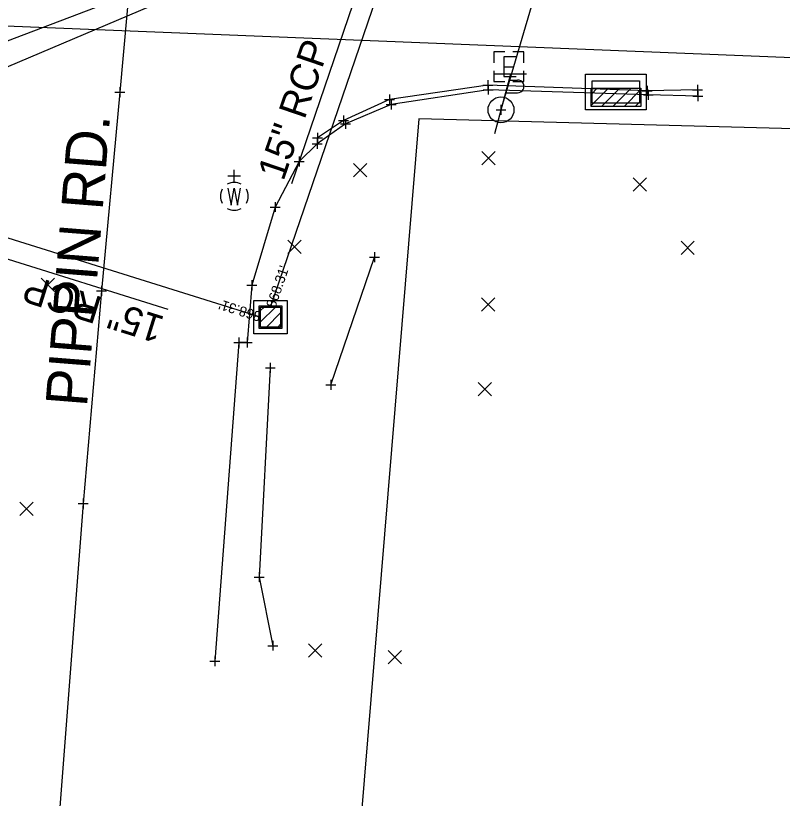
# Model space of a CAD drawing. Extents: x 1380550 to 1381945, y 468927 to 470496.
# Drawn here: x 1381608.3 to 1381685.3, y 470149.2 to 470227.8 of the extents above; entities that cross this region are included whole.
import ezdxf

# ---------------------------------------------------------------- set-up
doc = ezdxf.new("R2010")
doc.units = 0
for name, color, linetype in [('DR_X_Cells', 7, 'Continuous'), ('DR_X_Ditch', 7, 'Continuous'), ('DR_X_Storm_Sewer', 7, 'Continuous'), ('DR_X_Text', 7, 'Continuous'), ('GK_Drainage_Nodes', 7, 'Continuous'), ('PV_X_COP', 7, 'Continuous'), ('PV_X_Curb', 7, 'Continuous'), ('PV_X_EOP', 7, 'Continuous'), ('RD_X_Text', 7, 'Continuous'), ('RW_X_Esmt_General', 7, 'Continuous'), ('SC_Scratch1', 7, 'Continuous'), ('SV_X_Random_Point', 7, 'Continuous'), ('SV_X_Shot_Marker', 7, 'Continuous'), ('SV_X_Top_of_Bank', 7, 'Continuous'), ('UT_X_Electric', 7, 'Continuous'), ('UT_X_Electric_Cells', 7, 'Continuous'), ('UT_X_Misc_Cells', 7, 'Continuous'), ('UT_X_Telecom', 7, 'Continuous'), ('UT_X_Water_Cells', 7, 'Continuous')]:
    doc.layers.add(name, color=color, linetype=linetype)

msp = doc.modelspace()

# ---------------------------------------------------------------- linework, layer by layer
at = {"layer": 'DR_X_Cells'}
for p, q in [((1381666.074, 470218.798), (1381667.828, 470220.557)), ((1381666.074, 470219.931), (1381666.698, 470220.557)), ((1381667.13, 470218.724), (1381668.958, 470220.557)), ((1381668.259, 470218.724), (1381670.088, 470220.557)), ((1381669.389, 470218.724), (1381671.074, 470220.413)), ((1381670.519, 470218.724), (1381671.074, 470219.28)), ((1381632.757, 470196.945), (1381634.516, 470198.703)), ((1381632.757, 470198.076), (1381633.385, 470198.703)), ((1381633.356, 470196.412), (1381635.049, 470198.105)), ((1381634.487, 470196.412), (1381635.049, 470196.973))]:
    msp.add_line(p, q, dxfattribs=at)
for points in [[(1381665.532, 470221.974), (1381671.616, 470221.974), (1381671.616, 470218.39), (1381665.532, 470218.39)], [(1381666.199, 470221.307), (1381670.949, 470221.307), (1381670.949, 470219.057), (1381666.199, 470219.057)], [(1381666.074, 470220.557), (1381671.074, 470220.557), (1381671.074, 470218.724), (1381666.074, 470218.724)], [(1381632.236, 470199.224), (1381635.57, 470199.224), (1381635.57, 470195.891), (1381632.236, 470195.891)], [(1381632.757, 470198.703), (1381635.049, 470198.703), (1381635.049, 470196.412), (1381632.757, 470196.412)], [(1381632.903, 470198.558), (1381634.903, 470198.558), (1381634.903, 470196.558), (1381632.903, 470196.558)]]:
    msp.add_lwpolyline(points, close=True, dxfattribs=at)
at = {"layer": 'DR_X_Ditch'}
msp.add_lwpolyline([(1381633.879, 470192.462), (1381632.757, 470171.449), (1381634.143, 470164.552)], dxfattribs=at)
at = {"layer": 'DR_X_Storm_Sewer'}
for p, q in [((1381633.903, 470198.558), (1381646.794, 470236.273)), ((1381906.161, 470214.727), (1381603.055, 470226.96)), ((1381632.903, 470197.558), (1381601.076, 470207.52))]:
    msp.add_line(p, q, dxfattribs=at)
at = {"layer": 'DR_X_Text'}
for p, q in [((1381642.166, 470228.993), (1381635.993, 470210.933)), ((1381605.369, 470204.055), (1381623.583, 470198.353))]:
    msp.add_line(p, q, dxfattribs=at)
at = {"layer": 'GK_Drainage_Nodes'}
for p, q in [((1381668.574, 470221.974), (1381668.574, 470221.974)), ((1381668.574, 470221.307), (1381668.574, 470221.307)), ((1381666.199, 470220.182), (1381666.199, 470220.182)), ((1381668.574, 470220.557), (1381668.574, 470220.557)), ((1381668.574, 470220.557), (1381668.574, 470220.557)), ((1381668.574, 470220.182), (1381668.574, 470220.182)), ((1381670.949, 470220.182), (1381670.949, 470220.182)), ((1381668.574, 470219.057), (1381668.574, 470219.057)), ((1381668.574, 470218.39), (1381668.574, 470218.39)), ((1381633.903, 470199.224), (1381633.903, 470199.224)), ((1381633.903, 470198.558), (1381633.903, 470198.558)), ((1381632.903, 470197.558), (1381632.903, 470197.558)), ((1381633.903, 470197.558), (1381633.903, 470197.558)), ((1381633.903, 470197.558), (1381633.903, 470197.558)), ((1381633.903, 470197.558), (1381633.903, 470197.558)), ((1381634.903, 470197.558), (1381634.903, 470197.558)), ((1381633.903, 470196.558), (1381633.903, 470196.558)), ((1381633.903, 470195.891), (1381633.903, 470195.891))]:
    msp.add_line(p, q, dxfattribs=at)
at = {"layer": 'PV_X_COP'}
msp.add_lwpolyline([(1381627.408, 470324.235), (1381625.025, 470294.425), (1381622.344, 470259.947), (1381618.765, 470220.138), (1381616.919, 470200.188), (1381615.103, 470178.831), (1381610.946, 470124.776), (1381606.492, 470071.232), (1381602.26, 470019.361), (1381598.177, 469969.796), (1381595.011, 469928.064), (1381590.91, 469878.811), (1381589.36, 469859.114), (1381585.986, 469815.579), (1381581.288, 469760.779)], dxfattribs=at)
at = {"layer": 'PV_X_Curb'}
msp.add_lwpolyline([(1381676.791, 470219.75), (1381671.827, 470219.886), (1381655.739, 470220.402), (1381646.018, 470218.916), (1381641.43, 470216.955), (1381638.594, 470214.962)], dxfattribs=at)
at = {"layer": 'PV_X_EOP'}
msp.add_lwpolyline([(1381676.765, 470220.385), (1381671.708, 470220.296), (1381655.718, 470220.85), (1381645.835, 470219.405), (1381641.211, 470217.307), (1381638.618, 470215.563), (1381638.594, 470214.962), (1381636.765, 470213.193), (1381634.363, 470208.616), (1381632.01, 470200.77), (1381631.562, 470195.02), (1381630.708, 470194.999), (1381628.299, 470162.981)], dxfattribs=at)
at = {"layer": 'RW_X_Esmt_General'}
msp.add_lwpolyline([(1381783.194, 470213.888), (1381648.776, 470217.487), (1381563.79, 469189.032)], dxfattribs=at)
at = {"layer": 'SV_X_Random_Point'}
for p, q in [((1381655.103, 470212.868), (1381656.437, 470214.204)), ((1381655.103, 470214.204), (1381656.437, 470212.868)), ((1381642.237, 470211.656), (1381643.571, 470212.991)), ((1381642.237, 470212.991), (1381643.571, 470211.656)), ((1381670.301, 470210.201), (1381671.635, 470211.536)), ((1381670.301, 470211.536), (1381671.635, 470210.201)), ((1381635.644, 470203.939), (1381636.978, 470205.274)), ((1381635.644, 470205.274), (1381636.978, 470203.939)), ((1381675.11, 470203.861), (1381676.444, 470205.196)), ((1381675.11, 470205.196), (1381676.444, 470203.861)), ((1381610.886, 470200.127), (1381612.22, 470201.462)), ((1381610.886, 470201.462), (1381612.22, 470200.127)), ((1381655.079, 470198.144), (1381656.413, 470199.479)), ((1381655.079, 470199.479), (1381656.413, 470198.144)), ((1381654.744, 470189.642), (1381656.078, 470190.977)), ((1381654.744, 470190.977), (1381656.078, 470189.642)), ((1381608.724, 470177.633), (1381610.058, 470178.968)), ((1381608.724, 470178.968), (1381610.058, 470177.633)), ((1381637.706, 470163.411), (1381639.04, 470164.746)), ((1381637.706, 470164.746), (1381639.04, 470163.411)), ((1381645.711, 470162.721), (1381647.045, 470164.056)), ((1381645.711, 470164.056), (1381647.045, 470162.721))]:
    msp.add_line(p, q, dxfattribs=at)
at = {"layer": 'SV_X_Shot_Marker'}
for p, q in [((1381618.765, 470220.638), (1381618.765, 470219.638)), ((1381655.218, 470220.85), (1381656.218, 470220.85)), ((1381655.218, 470220.85), (1381656.218, 470220.85)), ((1381655.718, 470221.35), (1381655.718, 470220.35)), ((1381655.718, 470221.35), (1381655.718, 470220.35)), ((1381655.718, 470220.85), (1381655.718, 470220.85)), ((1381655.718, 470220.85), (1381655.718, 470220.85)), ((1381655.739, 470220.902), (1381655.739, 470219.902)), ((1381655.739, 470220.902), (1381655.739, 470219.902)), ((1381671.708, 470220.796), (1381671.708, 470219.796)), ((1381676.765, 470220.885), (1381676.765, 470219.885)), ((1381618.265, 470220.138), (1381619.265, 470220.138)), ((1381618.765, 470220.138), (1381618.765, 470220.138)), ((1381645.835, 470219.905), (1381645.835, 470218.905)), ((1381655.239, 470220.402), (1381656.239, 470220.402)), ((1381655.239, 470220.402), (1381656.239, 470220.402)), ((1381655.739, 470220.402), (1381655.739, 470220.402)), ((1381655.739, 470220.402), (1381655.739, 470220.402)), ((1381671.208, 470220.296), (1381672.208, 470220.296)), ((1381671.327, 470219.886), (1381672.327, 470219.886)), ((1381671.708, 470220.296), (1381671.708, 470220.296)), ((1381671.827, 470220.386), (1381671.827, 470219.386)), ((1381671.827, 470219.886), (1381671.827, 470219.886)), ((1381676.265, 470220.385), (1381677.265, 470220.385)), ((1381676.765, 470220.385), (1381676.765, 470220.385)), ((1381676.791, 470220.25), (1381676.791, 470219.25)), ((1381645.335, 470219.405), (1381646.335, 470219.405)), ((1381645.835, 470219.405), (1381645.835, 470219.405)), ((1381646.018, 470219.416), (1381646.018, 470218.416)), ((1381676.291, 470219.75), (1381677.291, 470219.75)), ((1381676.791, 470219.75), (1381676.791, 470219.75)), ((1381645.518, 470218.916), (1381646.518, 470218.916)), ((1381646.018, 470218.916), (1381646.018, 470218.916)), ((1381656.535, 470218.369), (1381657.535, 470218.369)), ((1381656.535, 470218.369), (1381657.535, 470218.369)), ((1381657.035, 470218.869), (1381657.035, 470217.869)), ((1381657.035, 470218.869), (1381657.035, 470217.869)), ((1381657.035, 470218.369), (1381657.035, 470218.369)), ((1381657.035, 470218.369), (1381657.035, 470218.369)), ((1381641.211, 470217.807), (1381641.211, 470216.807)), ((1381641.211, 470217.807), (1381641.211, 470216.807)), ((1381641.43, 470217.455), (1381641.43, 470216.455)), ((1381641.43, 470217.455), (1381641.43, 470216.455)), ((1381640.711, 470217.307), (1381641.711, 470217.307)), ((1381640.711, 470217.307), (1381641.711, 470217.307)), ((1381640.93, 470216.955), (1381641.93, 470216.955)), ((1381640.93, 470216.955), (1381641.93, 470216.955)), ((1381641.211, 470217.307), (1381641.211, 470217.307)), ((1381641.211, 470217.307), (1381641.211, 470217.307)), ((1381641.43, 470216.955), (1381641.43, 470216.955)), ((1381641.43, 470216.955), (1381641.43, 470216.955)), ((1381638.618, 470216.063), (1381638.618, 470215.063)), ((1381638.118, 470215.563), (1381639.118, 470215.563)), ((1381638.594, 470215.462), (1381638.594, 470214.462)), ((1381638.594, 470215.462), (1381638.594, 470214.462)), ((1381638.618, 470215.563), (1381638.618, 470215.563)), ((1381638.094, 470214.962), (1381639.094, 470214.962)), ((1381638.094, 470214.962), (1381639.094, 470214.962)), ((1381638.594, 470214.962), (1381638.594, 470214.962)), ((1381638.594, 470214.962), (1381638.594, 470214.962)), ((1381636.765, 470213.693), (1381636.765, 470212.693)), ((1381636.765, 470213.693), (1381636.765, 470212.693)), ((1381636.265, 470213.193), (1381637.265, 470213.193)), ((1381636.265, 470213.193), (1381637.265, 470213.193)), ((1381636.765, 470213.193), (1381636.765, 470213.193)), ((1381636.765, 470213.193), (1381636.765, 470213.193)), ((1381634.363, 470209.116), (1381634.363, 470208.116)), ((1381633.863, 470208.616), (1381634.863, 470208.616)), ((1381634.363, 470208.616), (1381634.363, 470208.616)), ((1381644.334, 470204.069), (1381644.334, 470203.069)), ((1381643.834, 470203.569), (1381644.834, 470203.569)), ((1381644.334, 470203.569), (1381644.334, 470203.569)), ((1381632.01, 470201.27), (1381632.01, 470200.27)), ((1381632.01, 470201.27), (1381632.01, 470200.27)), ((1381616.419, 470200.188), (1381617.419, 470200.188)), ((1381616.919, 470200.688), (1381616.919, 470199.688)), ((1381616.919, 470200.188), (1381616.919, 470200.188)), ((1381631.51, 470200.77), (1381632.51, 470200.77)), ((1381631.51, 470200.77), (1381632.51, 470200.77)), ((1381632.01, 470200.77), (1381632.01, 470200.77)), ((1381632.01, 470200.77), (1381632.01, 470200.77)), ((1381630.708, 470195.499), (1381630.708, 470194.499)), ((1381631.562, 470195.52), (1381631.562, 470194.52)), ((1381630.208, 470194.999), (1381631.208, 470194.999)), ((1381630.708, 470194.999), (1381630.708, 470194.999)), ((1381631.062, 470195.02), (1381632.062, 470195.02)), ((1381631.562, 470195.02), (1381631.562, 470195.02)), ((1381633.379, 470192.462), (1381634.379, 470192.462)), ((1381633.879, 470192.962), (1381633.879, 470191.962)), ((1381633.879, 470192.462), (1381633.879, 470192.462)), ((1381639.468, 470190.746), (1381640.468, 470190.746)), ((1381639.968, 470191.246), (1381639.968, 470190.246)), ((1381639.968, 470190.746), (1381639.968, 470190.746)), ((1381615.103, 470179.331), (1381615.103, 470178.331)), ((1381614.603, 470178.831), (1381615.603, 470178.831)), ((1381615.103, 470178.831), (1381615.103, 470178.831)), ((1381632.757, 470171.949), (1381632.757, 470170.949)), ((1381632.257, 470171.449), (1381633.257, 470171.449)), ((1381632.757, 470171.449), (1381632.757, 470171.449)), ((1381634.143, 470165.052), (1381634.143, 470164.052)), ((1381633.643, 470164.552), (1381634.643, 470164.552)), ((1381634.143, 470164.552), (1381634.143, 470164.552)), ((1381628.299, 470163.481), (1381628.299, 470162.481)), ((1381627.799, 470162.981), (1381628.799, 470162.981)), ((1381628.299, 470162.981), (1381628.299, 470162.981))]:
    msp.add_line(p, q, dxfattribs=at)
at = {"layer": 'SV_X_Top_of_Bank'}
msp.add_lwpolyline([(1381639.968, 470190.746), (1381644.334, 470203.569)], dxfattribs=at)
at = {"layer": 'UT_X_Electric'}
for points in [[(1381665.562, 470247.404), (1381595.795, 470220.833), (1381581.264, 470018.199), (1381571.968, 469887.64), (1381559.775, 469757.408), (1381543.86, 469565.781), (1381529.165, 469390.12), (1381515.279, 469203.101), (1381540.8, 469054.263)], [(1381665.562, 470247.404), (1381657.035, 470218.369)]]:
    msp.add_lwpolyline(points, dxfattribs=at)
at = {"layer": 'UT_X_Electric_Cells'}
for p, q in [((1381657.322, 470222.71), (1381658.322, 470222.71)), ((1381657.822, 470222.71), (1381657.822, 470222.71))]:
    msp.add_line(p, q, dxfattribs=at)
for points in [[(1381657.422, 470224.21), (1381656.322, 470224.21), (1381656.322, 470223.11)], [(1381659.322, 470223.11), (1381659.322, 470224.21), (1381658.222, 470224.21)], [(1381658.572, 470223.71), (1381657.322, 470223.71), (1381657.322, 470221.71), (1381658.572, 470221.71)], [(1381656.322, 470222.31), (1381656.322, 470221.21), (1381657.422, 470221.21)], [(1381658.222, 470221.21), (1381659.322, 470221.21), (1381659.322, 470222.31)]]:
    msp.add_lwpolyline(points, dxfattribs=at)
at = {"layer": 'UT_X_Misc_Cells'}
for p, q in [((1381657.998, 470221.969), (1381656.392, 470215.969)), ((1381659.598, 470221.969), (1381656.398, 470221.969)), ((1381657.838, 470221.369), (1381658.688, 470221.369)), ((1381657.497, 470220.094), (1381658.688, 470220.094))]:
    msp.add_line(p, q, dxfattribs=at)
msp.add_circle((1381657.035, 470218.369), 1.3, dxfattribs=at)
msp.add_arc((1381658.701, 470220.732), 0.638, 268.8767, 91.1233, dxfattribs=at)
at = {"layer": 'UT_X_Telecom'}
msp.add_lwpolyline([(1381665.562, 470247.404), (1381595.346, 470217.51), (1381581.264, 470018.199), (1381571.968, 469887.64), (1381559.775, 469757.408), (1381543.86, 469565.781), (1381529.165, 469390.12), (1381515.279, 469203.101), (1381540.8, 469054.263)], dxfattribs=at)
at = {"layer": 'UT_X_Water_Cells'}
for p, q in [((1381630.263, 470211.092), (1381630.263, 470212.364)), ((1381630.898, 470211.729), (1381629.626, 470211.729)), ((1381630.263, 470209.692), (1381630.263, 470209.692))]:
    msp.add_line(p, q, dxfattribs=at)
msp.add_lwpolyline([(1381629.626, 470210.512), (1381629.945, 470208.789), (1381630.263, 470210.512), (1381630.583, 470208.789), (1381630.9, 470210.512)], dxfattribs=at)
for start, end in [(150.01836, 209.98164), (60.01836, 120.01574), (330.01836, 29.98164), (239.98426, 299.98164)]:
    msp.add_arc((1381630.263, 470209.694), 1.4, start, end, dxfattribs=at)

# ---------------------------------------------------------------- texts
at = {"layer": 'DR_X_Text'}
for rotation, p in [(71.12967, (1381635.194, 470211.143)), (162.61865, (1381623.394, 470197.549))]:
    msp.add_text('15" RCP', height=2.8, rotation=rotation, dxfattribs=at).set_placement(p)
at = {"layer": 'RD_X_Text'}
msp.add_text('PIPPIN RD.', height=4.1667, rotation=85.44278, dxfattribs=at).set_placement((1381615.464, 470188.469))
at = {"layer": 'SC_Scratch1'}
for rotation, p in [(71.12967, (1381634.376, 470198.396)), (162.61865, (1381633.052, 470198.035))]:
    msp.add_text("868.31'", height=1, rotation=rotation, dxfattribs=at).set_placement(p)

doc.saveas('drawing.dxf')
